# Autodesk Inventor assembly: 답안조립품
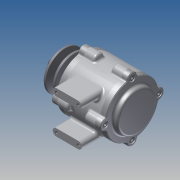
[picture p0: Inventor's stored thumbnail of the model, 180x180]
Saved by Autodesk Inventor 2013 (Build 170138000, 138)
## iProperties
Created: 2015-03
Part Number: 답안조립품
Document SubType Name: Assembly
Designer: kb543
Author: kb543
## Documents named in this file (11)
- C:\Users\kb543\Desktop\450305V1004\답안조립품.iam
- C:\Users\kb543\Desktop\450305V1004\본체.ipt
- C:\Users\kb543\Desktop\450305V1004\축.ipt
- C:\Users\kb543\Desktop\450305V1004\V벨트풀리.ipt
- C:\Users\kb543\Desktop\450305V1004\키(4 x 4 x 12).ipt
- C:\Users\kb543\Desktop\450305V1004\너트 M12x1.25.ipt
- C:\Users\kb543\Desktop\450305V1004\커버.ipt
- C:\Users\kb543\Desktop\450305V1004\커버2.ipt
- C:\Users\kb543\Desktop\450305V1004\베어링 6204.ipt
- C:\Users\kb543\Desktop\450305V1004\오일실.ipt
- C:\Users\kb543\Desktop\450305V1004\M 4 x 12.ipt
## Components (14 placed, 6 different names)
1. 그루브 풀리1:1
2. KS B 1311 (I) 4 x 4 x 12:1
3. KS B 1012 클래스 1 일반 - 미터 M12x1.25:1
4. KS B 2023 6204 - 20 x 47 x 14:1
5. KS B 2023 6204 - 20 x 47 x 14:2
6. KS B 2804 D D - 20 32 8:1
7. KS B 1003 - 미터 M 4 x 12:5
8. KS B 1003 - 미터 M 4 x 12:6
9. KS B 1003 - 미터 M 4 x 12:7
10. KS B 1003 - 미터 M 4 x 12:8
11. KS B 1003 - 미터 M 4 x 12:1
12. KS B 1003 - 미터 M 4 x 12:2
13. KS B 1003 - 미터 M 4 x 12:3
14. KS B 1003 - 미터 M 4 x 12:4
